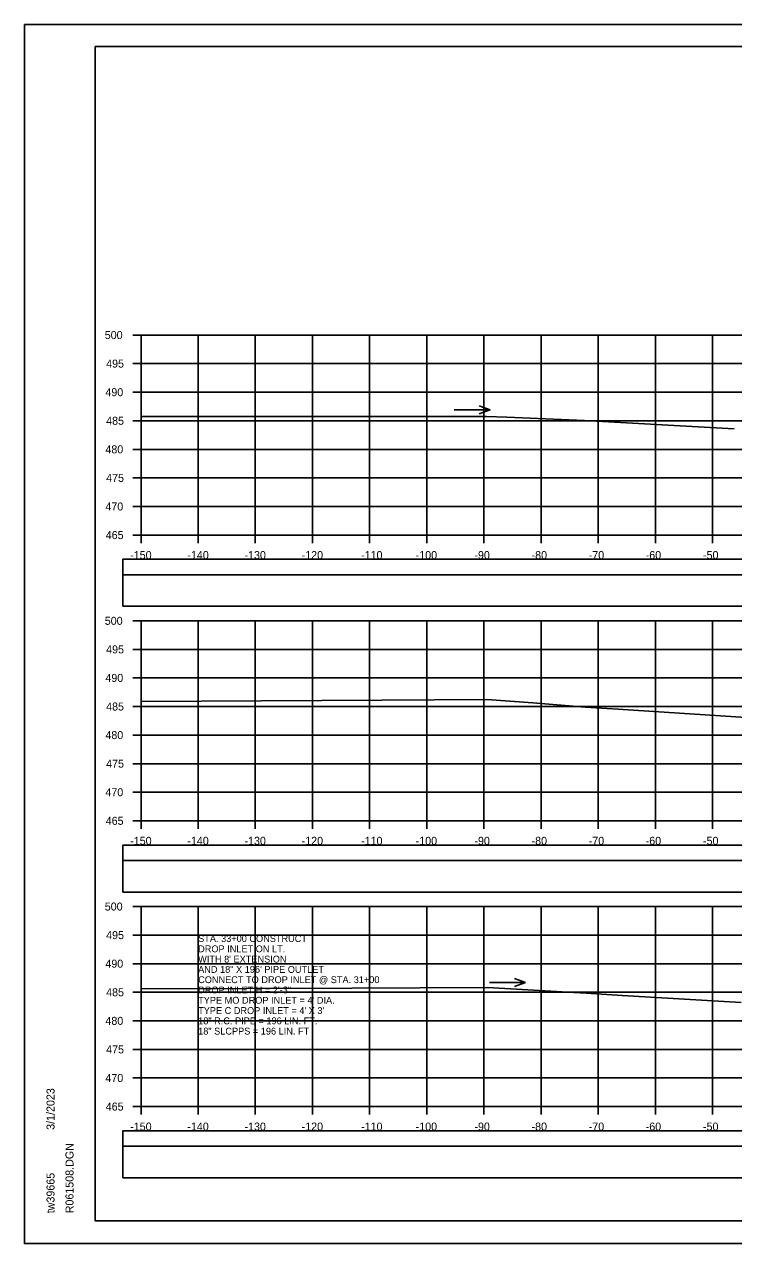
# Model space of a CAD drawing. Extents: x 1371057 to 1372761, y 380005 to 390517.
# Drawn here: x 1371390.5 to 1371514.6, y 380645.1 to 380858.4 of the extents above; entities that cross this region are included whole.
import ezdxf

# ---------------------------------------------------------------- set-up
doc = ezdxf.new("R2010")
doc.units = 0
for name, color, linetype in [('R_Axis', 7, 'Continuous'), ('R_Axis Annot', 7, 'Continuous'), ('R_Border', 7, 'Continuous'), ('R_Detour', 7, 'Continuous'), ('R_Dimension', 7, 'Continuous'), ('R_Exist Surface', 7, 'Continuous'), ('R_Grid', 7, 'Continuous'), ('R_No Plot', 7, 'Continuous'), ('R_Water Annot', 7, 'Continuous')]:
    doc.layers.add(name, color=color, linetype=linetype)

msp = doc.modelspace()

# ---------------------------------------------------------------- linework, layer by layer
at = {"layer": 'R_Axis'}
for p, q in [((1371409.47, 380804.07), (1371410.87, 380804.07)), ((1371410.87, 380769.07), (1371410.87, 380804.07)), ((1371409.47, 380799.07), (1371410.87, 380799.07)), ((1371409.47, 380794.07), (1371410.87, 380794.07)), ((1371409.47, 380789.07), (1371410.87, 380789.07)), ((1371409.47, 380784.07), (1371410.87, 380784.07)), ((1371409.47, 380779.07), (1371410.87, 380779.07)), ((1371409.47, 380774.07), (1371410.87, 380774.07)), ((1371409.47, 380769.07), (1371410.87, 380769.07)), ((1371410.87, 380769.07), (1371710.87, 380769.07)), ((1371410.87, 380767.67), (1371410.87, 380769.07)), ((1371420.87, 380767.67), (1371420.87, 380769.07)), ((1371430.87, 380767.67), (1371430.87, 380769.07)), ((1371440.87, 380767.67), (1371440.87, 380769.07)), ((1371450.87, 380767.67), (1371450.87, 380769.07)), ((1371460.87, 380767.67), (1371460.87, 380769.07)), ((1371470.87, 380767.67), (1371470.87, 380769.07)), ((1371480.87, 380767.67), (1371480.87, 380769.07)), ((1371490.87, 380767.67), (1371490.87, 380769.07)), ((1371500.87, 380767.67), (1371500.87, 380769.07)), ((1371510.87, 380767.67), (1371510.87, 380769.07)), ((1371409.47, 380754.07), (1371410.87, 380754.07)), ((1371410.87, 380719.07), (1371410.87, 380754.07)), ((1371409.47, 380749.07), (1371410.87, 380749.07)), ((1371409.47, 380744.07), (1371410.87, 380744.07)), ((1371409.47, 380739.07), (1371410.87, 380739.07)), ((1371409.47, 380734.07), (1371410.87, 380734.07)), ((1371409.47, 380729.07), (1371410.87, 380729.07)), ((1371409.47, 380724.07), (1371410.87, 380724.07)), ((1371409.47, 380719.07), (1371410.87, 380719.07)), ((1371410.87, 380719.07), (1371710.87, 380719.07)), ((1371410.87, 380717.67), (1371410.87, 380719.07)), ((1371420.87, 380717.67), (1371420.87, 380719.07)), ((1371430.87, 380717.67), (1371430.87, 380719.07)), ((1371440.87, 380717.67), (1371440.87, 380719.07)), ((1371450.87, 380717.67), (1371450.87, 380719.07)), ((1371460.87, 380717.67), (1371460.87, 380719.07)), ((1371470.87, 380717.67), (1371470.87, 380719.07)), ((1371480.87, 380717.67), (1371480.87, 380719.07)), ((1371490.87, 380717.67), (1371490.87, 380719.07)), ((1371500.87, 380717.67), (1371500.87, 380719.07)), ((1371510.87, 380717.67), (1371510.87, 380719.07)), ((1371409.47, 380704.07), (1371410.87, 380704.07)), ((1371410.87, 380669.07), (1371410.87, 380704.07)), ((1371409.47, 380699.07), (1371410.87, 380699.07)), ((1371409.47, 380694.07), (1371410.87, 380694.07)), ((1371409.47, 380689.07), (1371410.87, 380689.07)), ((1371409.47, 380684.07), (1371410.87, 380684.07)), ((1371409.47, 380679.07), (1371410.87, 380679.07)), ((1371409.47, 380674.07), (1371410.87, 380674.07)), ((1371409.47, 380669.07), (1371410.87, 380669.07)), ((1371410.87, 380669.07), (1371710.87, 380669.07)), ((1371410.87, 380667.67), (1371410.87, 380669.07)), ((1371420.87, 380667.67), (1371420.87, 380669.07)), ((1371430.87, 380667.67), (1371430.87, 380669.07)), ((1371440.87, 380667.67), (1371440.87, 380669.07)), ((1371450.87, 380667.67), (1371450.87, 380669.07)), ((1371460.87, 380667.67), (1371460.87, 380669.07)), ((1371470.87, 380667.67), (1371470.87, 380669.07)), ((1371480.87, 380667.67), (1371480.87, 380669.07)), ((1371490.87, 380667.67), (1371490.87, 380669.07)), ((1371500.87, 380667.67), (1371500.87, 380669.07)), ((1371510.87, 380667.67), (1371510.87, 380669.07))]:
    msp.add_line(p, q, dxfattribs=at)
at = {"layer": 'R_Border'}
for p, q in [((1371402.87, 380854.53), (1371719.05, 380854.53)), ((1371402.87, 380649.07), (1371402.87, 380854.53)), ((1371402.87, 380649.07), (1371402.87, 380649.07)), ((1371719.05, 380649.07), (1371402.87, 380649.07))]:
    msp.add_line(p, q, dxfattribs=at)
at = {"layer": 'R_Detour'}
for points in [[(1371407.72, 380762.12), (1371714.03, 380762.12), (1371714.03, 380764.83), (1371407.72, 380764.83)], [(1371407.72, 380712.12), (1371714.03, 380712.12), (1371714.03, 380714.83), (1371407.72, 380714.83)], [(1371407.72, 380662.12), (1371714.03, 380662.12), (1371714.03, 380664.83), (1371407.72, 380664.83)]]:
    msp.add_lwpolyline(points, close=True, dxfattribs=at)
at = {"layer": 'R_Dimension'}
for points in [[(1371407.72, 380756.6), (1371714.03, 380756.6), (1371714.03, 380762.12), (1371407.72, 380762.12)], [(1371407.72, 380706.6), (1371714.03, 380706.6), (1371714.03, 380712.12), (1371407.72, 380712.12)], [(1371407.72, 380656.6), (1371714.03, 380656.6), (1371714.03, 380662.12), (1371407.72, 380662.12)]]:
    msp.add_lwpolyline(points, close=True, dxfattribs=at)
at = {"layer": 'R_Exist Surface'}
for points in [[(1371410.87, 380789.79), (1371450.18, 380789.8), (1371471.33, 380789.82), (1371474.87, 380789.69), (1371488.46, 380789.12), (1371514.66, 380787.68)], [(1371410.87, 380739.96), (1371452.99, 380740.18), (1371471.37, 380740.27), (1371479.46, 380739.69), (1371488.6, 380738.98), (1371494.39, 380738.61), (1371520.3, 380736.92)], [(1371410.87, 380689.66), (1371447.77, 380689.76), (1371471.57, 380689.88), (1371485.56, 380689.09), (1371488.77, 380688.92), (1371495.09, 380688.53), (1371515.91, 380687.3)]]:
    msp.add_lwpolyline(points, dxfattribs=at)
at = {"layer": 'R_Grid'}
for p, q in [((1371410.87, 380804.07), (1371710.87, 380804.07)), ((1371410.87, 380769.07), (1371410.87, 380804.07)), ((1371420.87, 380769.07), (1371420.87, 380804.07)), ((1371430.87, 380769.07), (1371430.87, 380804.07)), ((1371440.87, 380769.07), (1371440.87, 380804.07)), ((1371450.87, 380769.07), (1371450.87, 380804.07)), ((1371460.87, 380769.07), (1371460.87, 380804.07)), ((1371470.87, 380769.07), (1371470.87, 380804.07)), ((1371480.87, 380769.07), (1371480.87, 380804.07)), ((1371490.87, 380769.07), (1371490.87, 380804.07)), ((1371500.87, 380769.07), (1371500.87, 380804.07)), ((1371510.87, 380769.07), (1371510.87, 380804.07)), ((1371410.87, 380799.07), (1371710.87, 380799.07)), ((1371410.87, 380794.07), (1371710.87, 380794.07)), ((1371410.87, 380789.07), (1371710.87, 380789.07)), ((1371410.87, 380784.07), (1371710.87, 380784.07)), ((1371410.87, 380779.07), (1371710.87, 380779.07)), ((1371410.87, 380774.07), (1371710.87, 380774.07)), ((1371410.87, 380769.07), (1371710.87, 380769.07)), ((1371410.87, 380754.07), (1371710.87, 380754.07)), ((1371410.87, 380719.07), (1371410.87, 380754.07)), ((1371420.87, 380719.07), (1371420.87, 380754.07)), ((1371430.87, 380719.07), (1371430.87, 380754.07)), ((1371440.87, 380719.07), (1371440.87, 380754.07)), ((1371450.87, 380719.07), (1371450.87, 380754.07)), ((1371460.87, 380719.07), (1371460.87, 380754.07)), ((1371470.87, 380719.07), (1371470.87, 380754.07)), ((1371480.87, 380719.07), (1371480.87, 380754.07)), ((1371490.87, 380719.07), (1371490.87, 380754.07)), ((1371500.87, 380719.07), (1371500.87, 380754.07)), ((1371510.87, 380719.07), (1371510.87, 380754.07)), ((1371410.87, 380749.07), (1371710.87, 380749.07)), ((1371410.87, 380744.07), (1371710.87, 380744.07)), ((1371410.87, 380739.07), (1371710.87, 380739.07)), ((1371410.87, 380734.07), (1371710.87, 380734.07)), ((1371410.87, 380729.07), (1371710.87, 380729.07)), ((1371410.87, 380724.07), (1371710.87, 380724.07)), ((1371410.87, 380719.07), (1371710.87, 380719.07)), ((1371410.87, 380704.07), (1371710.87, 380704.07)), ((1371410.87, 380669.07), (1371410.87, 380704.07)), ((1371420.87, 380669.07), (1371420.87, 380704.07)), ((1371430.87, 380669.07), (1371430.87, 380704.07)), ((1371440.87, 380669.07), (1371440.87, 380704.07)), ((1371450.87, 380669.07), (1371450.87, 380704.07)), ((1371460.87, 380669.07), (1371460.87, 380704.07)), ((1371470.87, 380669.07), (1371470.87, 380704.07)), ((1371480.87, 380669.07), (1371480.87, 380704.07)), ((1371490.87, 380669.07), (1371490.87, 380704.07)), ((1371500.87, 380669.07), (1371500.87, 380704.07)), ((1371510.87, 380669.07), (1371510.87, 380704.07)), ((1371410.87, 380699.07), (1371710.87, 380699.07)), ((1371410.87, 380694.07), (1371710.87, 380694.07)), ((1371410.87, 380689.07), (1371710.87, 380689.07)), ((1371410.87, 380684.07), (1371710.87, 380684.07)), ((1371410.87, 380679.07), (1371710.87, 380679.07)), ((1371410.87, 380674.07), (1371710.87, 380674.07)), ((1371410.87, 380669.07), (1371710.87, 380669.07))]:
    msp.add_line(p, q, dxfattribs=at)
at = {"layer": 'R_No Plot'}
for p, q in [((1371390.47, 380858.43), (1371723.8, 380858.43)), ((1371390.47, 380645.09), (1371723.8, 380645.09))]:
    msp.add_line(p, q, dxfattribs=at)
for points in [[(1371390.46, 380858.43), (1371723.8, 380858.43), (1371723.8, 380645.09), (1371390.46, 380645.09)], [(1371636.79, 380854.53), (1371656.41, 380854.53), (1371656.41, 380844.65), (1371672.52, 380844.65), (1371695.72, 380844.65), (1371695.84, 380816.5), (1371719.05, 380816.5), (1371719.05, 380649.07), (1371402.87, 380649.07), (1371402.87, 380854.53)]]:
    msp.add_lwpolyline(points, close=True, dxfattribs=at)
at = {"layer": 'R_Water Annot'}
for p, q in [((1371465.69, 380790.98), (1371471.97, 380790.98)), ((1371471.97, 380790.98), (1371470.05, 380791.68)), ((1371471.97, 380790.98), (1371470.05, 380790.28)), ((1371471.86, 380690.78), (1371478.15, 380690.78)), ((1371478.15, 380690.78), (1371476.23, 380691.48)), ((1371478.15, 380690.78), (1371476.23, 380690.08))]:
    msp.add_line(p, q, dxfattribs=at)

# ---------------------------------------------------------------- texts
at = {"layer": 'R_Axis Annot'}
for s, p in [('500', (1371404.53, 380803.37)), ('495', (1371404.77, 380798.37)), ('490', (1371404.64, 380793.37)), ('485', (1371404.77, 380788.37)), ('480', (1371404.64, 380783.37)), ('475', (1371404.77, 380778.37)), ('470', (1371404.64, 380773.37)), ('465', (1371404.7, 380768.37)), ('-150', (1371408.98, 380764.87)), ('-140', (1371418.98, 380764.87)), ('-130', (1371428.98, 380764.87)), ('-120', (1371438.98, 380764.87)), ('-110', (1371449.38, 380764.87)), ('-100', (1371458.93, 380764.87)), ('-90', (1371469.21, 380764.87)), ('-80', (1371479.21, 380764.87)), ('-70', (1371489.21, 380764.87)), ('-60', (1371499.18, 380764.87)), ('-50', (1371509.21, 380764.87)), ('500', (1371404.53, 380753.37)), ('495', (1371404.77, 380748.37)), ('490', (1371404.64, 380743.37)), ('485', (1371404.77, 380738.37)), ('480', (1371404.64, 380733.37)), ('475', (1371404.77, 380728.37)), ('470', (1371404.64, 380723.37)), ('465', (1371404.7, 380718.37)), ('-150', (1371408.98, 380714.87)), ('-140', (1371418.98, 380714.87)), ('-130', (1371428.98, 380714.87)), ('-120', (1371438.98, 380714.87)), ('-110', (1371449.38, 380714.87)), ('-100', (1371458.93, 380714.87)), ('-90', (1371469.21, 380714.87)), ('-80', (1371479.21, 380714.87)), ('-70', (1371489.21, 380714.87)), ('-60', (1371499.18, 380714.87)), ('-50', (1371509.21, 380714.87)), ('500', (1371404.53, 380703.37)), ('495', (1371404.77, 380698.37)), ('490', (1371404.64, 380693.37)), ('485', (1371404.77, 380688.37)), ('480', (1371404.64, 380683.37)), ('475', (1371404.77, 380678.37)), ('470', (1371404.64, 380673.37)), ('465', (1371404.7, 380668.37)), ('-150', (1371408.98, 380664.87)), ('-140', (1371418.98, 380664.87)), ('-130', (1371428.98, 380664.87)), ('-120', (1371438.98, 380664.87)), ('-110', (1371449.38, 380664.87)), ('-100', (1371458.93, 380664.87)), ('-90', (1371469.21, 380664.87)), ('-80', (1371479.21, 380664.87)), ('-70', (1371489.21, 380664.87)), ('-60', (1371499.18, 380664.87)), ('-50', (1371509.21, 380664.87))]:
    msp.add_text(s, height=1.4, dxfattribs=at).set_placement(p)
at = {"layer": 'R_Border'}
for s, p in [('3/1/2023', (1371395.74, 380665)), ('R061508.DGN', (1371399.06, 380650.4)), ('tw39665', (1371395.74, 380650.4))]:
    msp.add_text(s, height=1.4, rotation=90, dxfattribs=at).set_placement(p)
at = {"layer": 'R_Water Annot'}
for s, p in [('STA. 33+00 CONSTRUCT', (1371420.87, 380697.87)), ('DROP INLET ON LT.', (1371420.87, 380696.07)), ("WITH 8' EXTENSION", (1371420.87, 380694.27)), ('AND 18" X 196\' PIPE OUTLET', (1371420.87, 380692.47)), ('CONNECT TO DROP INLET @ STA. 31+00', (1371420.87, 380690.67)), ("TYPE MO DROP INLET = 4' DIA.", (1371420.87, 380687.07)), ('DROP INLET H = 2\'-3"', (1371420.87, 380688.87)), ("TYPE C DROP INLET = 4' X 3'", (1371420.87, 380685.27)), ('18" R.C. PIPE = 196 LIN. FT.', (1371420.87, 380683.47)), ('18" SLCPPS = 196 LIN. FT', (1371420.87, 380681.67))]:
    msp.add_text(s, height=1.2, dxfattribs=at).set_placement(p)

doc.saveas('drawing.dxf')
